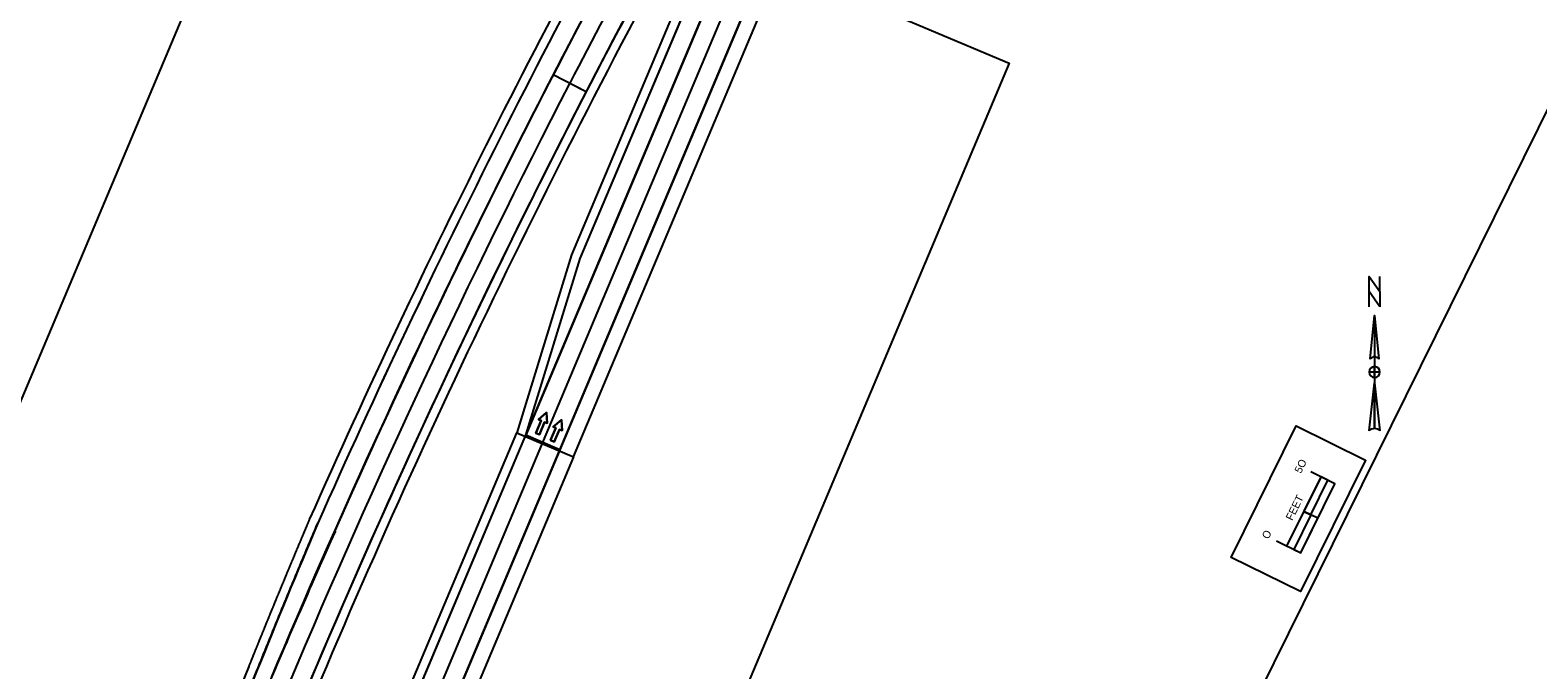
# Model space of a CAD drawing. Extents: x 14104283 to 14120882, y 8635219 to 8671666.
# Drawn here: x 14118496 to 14119473, y 8668018 to 8668432 of the extents above; entities that cross this region are included whole.
import ezdxf

# ---------------------------------------------------------------- set-up
doc = ezdxf.new("R2010")
doc.units = 0
for name, color, linetype in [('Default', 7, 'Continuous'), ('dsnCellsNorthArrow', 7, 'Continuous'), ('dsnCellsScaleBlock', 7, 'Continuous'), ('dsnNonPlotable', 7, 'Continuous'), ('dsnPaintExistingBrokenLaneLineWhite', 7, 'Continuous'), ('dsnPaintExistingDottedLineWhite', 7, 'Continuous'), ('dsnPaintExistingEdgeLineLeftYellow', 7, 'Continuous'), ('dsnPaintExistingEdgeLineRightWhite', 7, 'Continuous'), ('dsnPaintExistingLaneLineWhite', 7, 'Continuous'), ('dsnShadingPaved', 7, 'Continuous'), ('dsnStgShadingPrevPav', 7, 'Continuous'), ('Level 2', 7, 'Continuous'), ('Level 5', 7, 'Continuous')]:
    doc.layers.add(name, color=color, linetype=linetype)

msp = doc.modelspace()

# ---------------------------------------------------------------- linework, layer by layer
at = {"layer": 'Default'}
for p, q in [((14118835.25, 8668403.13), (14118856.57, 8668392.12)), ((14118845.91, 8668397.62), (14118856.57, 8668392.12)), ((14118693.64, 8668107.64), (14118694.07, 8668107.45)), ((14118528.39, 8667730.93), (14118643.53, 8668017.62))]:
    msp.add_line(p, q, dxfattribs=at)
for centre, radius, start, end in [((14121955.85, 8666791.92), 3512, 144.95493, 152.69211), ((14123732.96, 8665874.38), 5512, 149.67774, 156.09858), ((14123732.96, 8665874.38), 5524, 150.3689, 153.23374), ((14121955.85, 8666791.92), 3488, 149.50762, 152.69211), ((14123732.96, 8665874.38), 5512, 152.69211, 153.16925), ((14123732.96, 8665874.38), 5488, 152.69211, 157.1633), ((14123732.96, 8665874.38), 5512, 153.16925, 157.1633), ((14123732.96, 8665874.38), 5524, 153.23374, 156.09858), ((14123767.91, 8665959.11), 5522.39, 157.04925, 158.11426), ((14123265.63, 8666052.94), 5012, 155.80033, 157.1633)]:
    msp.add_arc(centre, radius, start, end, dxfattribs=at)
at = {"layer": 'dsnCellsNorthArrow'}
for p, q in [((14119367.21, 8668247.06), (14119370.02, 8668218.89)), ((14119367.21, 8668247.06), (14119367.21, 8668173.81)), ((14119364.39, 8668218.89), (14119364.39, 8668218.89)), ((14119364.5, 8668219.15), (14119365.02, 8668219.73)), ((14119363.68, 8668172.4), (14119367.21, 8668203.39)), ((14119367.21, 8668206.91), (14119367.21, 8668206.91))]:
    msp.add_line(p, q, dxfattribs=at)
msp.add_lwpolyline([(14119370.73, 8668252.69), (14119363.68, 8668262.55), (14119363.68, 8668272.41), (14119370.73, 8668262.55)], close=True, dxfattribs=at)
for points in [[(14119363.68, 8668252.69), (14119363.68, 8668272.41), (14119370.73, 8668262.55), (14119370.73, 8668272.41)], [(14119364.39, 8668218.89), (14119367.21, 8668247.06), (14119367.21, 8668220.3)], [(14119367.21, 8668206.91), (14119367.21, 8668210.44), (14119363.68, 8668210.44)], [(14119370.73, 8668210.44), (14119367.21, 8668210.44), (14119367.21, 8668213.96)], [(14119367.21, 8668173.81), (14119367.21, 8668203.39), (14119370.73, 8668172.4)]]:
    msp.add_lwpolyline(points, dxfattribs=at)
for centre, radius, start, end in [((14119367.21, 8668216.77), 3.52, 90.02039, 143.12574), ((14119367.21, 8668216.78), 3.52, 36.84806, 90.02184), ((14119367.21, 8668210.44), 3.52, 90, 180), ((14119367.21, 8668210.44), 3.52, 180, 270), ((14119367.21, 8668210.44), 3.52, 0, 90), ((14119367.21, 8668210.44), 3.52, 270, 360), ((14119367.21, 8668168.71), 5.1, 89.98939, 133.61895), ((14119367.21, 8668168.71), 5.11, 46.40206, 90.00064)]:
    msp.add_arc(centre, radius, start, end, dxfattribs=at)
at = {"layer": 'dsnCellsScaleBlock'}
msp.add_line((14119330.43, 8668115.73), (14119321.47, 8668120.16), dxfattribs=at)
msp.add_line((14119330.43, 8668115.73), (14119321.47, 8668120.16), dxfattribs=at)
for points in [[(14119274.42, 8668090.43), (14119316.53, 8668175.59), (14119361.35, 8668153.43), (14119319.24, 8668068.27)], [(14119319.24, 8668068.27), (14119274.42, 8668090.43), (14119316.53, 8668175.59), (14119361.35, 8668153.43)], [(14119325.92, 8668117.96), (14119337, 8668140.37), (14119332.55, 8668142.57), (14119321.47, 8668120.16)], [(14119319.35, 8668093.32), (14119330.43, 8668115.73), (14119325.92, 8668117.96), (14119314.84, 8668095.55)]]:
    msp.add_lwpolyline(points, close=True, dxfattribs=at)
for points in [[(14119303.67, 8668101.07), (14119319.35, 8668093.32), (14119341.51, 8668138.14), (14119325.83, 8668145.89)], [(14119310.39, 8668097.75), (14119332.55, 8668142.57)]]:
    msp.add_lwpolyline(points, dxfattribs=at)
at = {"layer": 'dsnNonPlotable'}
for points in [[(14118092.03, 8667853.71), (14118786.76, 8669258.84), (14119692.14, 8668811.2), (14118997.41, 8667406.07)], [(14118056.48, 8667161.91), (14118665.06, 8668606.45), (14119130.44, 8668410.38), (14118521.87, 8666965.84)]]:
    msp.add_lwpolyline(points, close=True, dxfattribs=at)
at = {"layer": 'dsnPaintExistingBrokenLaneLineWhite'}
for p, q in [((14118863.73, 8668248.6), (14118951.74, 8668457.58)), ((14114932.53, 8658913.38), (14118863.73, 8668248.6))]:
    msp.add_line(p, q, dxfattribs=at)
for centre, radius, start, end in [((14121955.85, 8666791.92), 3500, 149.50762, 152.69211), ((14123732.96, 8665874.38), 5500, 152.69211, 157.1633)]:
    msp.add_arc(centre, radius, start, end, dxfattribs=at)
at = {"layer": 'dsnPaintExistingDottedLineWhite'}
msp.add_arc((14123732.96, 8665874.38), 5512, 152.23375, 154.51073, dxfattribs=at)
at = {"layer": 'dsnPaintExistingEdgeLineLeftYellow'}
for p, q in [((14118852.57, 8668283.93), (14118948.15, 8668509.94)), ((14118817.44, 8668169.6), (14118852.57, 8668283.93)), ((14115900.95, 8661243.95), (14118817.44, 8668169.6))]:
    msp.add_line(p, q, dxfattribs=at)
for centre, radius, start, end in [((14121955.85, 8666791.92), 3488, 149.50762, 152.69211), ((14123732.96, 8665874.38), 5488, 152.69211, 157.1633)]:
    msp.add_arc(centre, radius, start, end, dxfattribs=at)
at = {"layer": 'dsnPaintExistingEdgeLineRightWhite'}
for p, q in [((14118874.68, 8668243.67), (14118962.79, 8668452.92)), ((14110924.38, 8649364.51), (14118874.67, 8668243.66)), ((14118643.53, 8668017.62), (14118412.94, 8667444.38))]:
    msp.add_line(p, q, dxfattribs=at)
for centre, radius, start, end in [((14123732.96, 8665874.38), 5524, 150.3689, 156.09858), ((14123767.91, 8665959.11), 5522.39, 157.04925, 158.11426)]:
    msp.add_arc(centre, radius, start, end, dxfattribs=at)
at = {"layer": 'dsnPaintExistingLaneLineWhite'}
msp.add_line((14118863.63, 8668279.27), (14118940.68, 8668462.24), dxfattribs=at)
at = {"layer": 'dsnShadingPaved'}
for points in [[(14118817.44, 8668169.6), (14118852.57, 8668283.93), (14118948.15, 8668509.94), (14118959.14, 8668505.1), (14118940.68, 8668462.24)], [(14118817.44, 8668169.6), (14118940.68, 8668462.24), (14118962.79, 8668452.92), (14118874.67, 8668243.66), (14118839.45, 8668160.02)], [(14118227.72, 8666769.23), (14118817.44, 8668169.6), (14118839.45, 8668160.02), (14118249.84, 8666759.92)]]:
    msp.add_lwpolyline(points, close=True, dxfattribs=at)
at = {"layer": 'dsnStgShadingPrevPav'}
for p, q in [((14118924.09, 8668469.22), (14118847.04, 8668286.26)), ((14118848.39, 8668155.49), (14118972.01, 8668449.04)), ((14118847.04, 8668286.26), (14118811.53, 8668171.01)), ((14115895.65, 8661246.83), (14118811.53, 8668171.01)), ((14118811.53, 8668171.01), (14118848.39, 8668155.49)), ((14118811.53, 8668171.01), (14118848.39, 8668155.49)), ((14118848.39, 8668155.49), (14115932.51, 8661231.3)), ((14118637.96, 8668019.85), (14118497.16, 8667669.27))]:
    msp.add_line(p, q, dxfattribs=at)
for centre, radius, start, end in [((14123732.96, 8665874.38), 5512, 146.42562, 157.1633), ((14123732.96, 8665874.38), 5488, 146.42119, 157.1633), ((14123732.96, 8665874.38), 5530, 150.3689, 156.09911), ((14123732.59, 8665873.82), 5512, 150.36196, 157.1633), ((14123732.96, 8665874.38), 5524, 150.3689, 156.09858), ((14123732.96, 8665874.38), 5524, 150.3689, 156.09858), ((14123732.96, 8665874.38), 5488, 150.67095, 157.1633), ((14123732.96, 8665874.38), 5482, 150.67097, 157.1633)]:
    msp.add_arc(centre, radius, start, end, dxfattribs=at)
for points, degree in [([(14118677.15, 8668114.84), (14118676.77, 8668113.95), (14118675.45, 8668110.85), (14118673.07, 8668105.18), (14118671.18, 8668100.7), (14118669.16, 8668095.89), (14118667.19, 8668091.17), (14118665.21, 8668086.42), (14118663.23, 8668081.68), (14118661.26, 8668076.94), (14118659.29, 8668072.19), (14118657.33, 8668067.44), (14118655.38, 8668062.69), (14118653.42, 8668057.94), (14118651.47, 8668053.18), (14118649.53, 8668048.43), (14118647.59, 8668043.66), (14118645.66, 8668038.92), (14118643.7, 8668034.09), (14118641.88, 8668029.58), (14118639.58, 8668023.88), (14118638.32, 8668020.76), (14118637.96, 8668019.85)], 2), ([(14118643.53, 8668017.62), (14118644.16, 8668019.2), (14118645.44, 8668022.38), (14118647.36, 8668027.14), (14118649.28, 8668031.89), (14118651.21, 8668036.65), (14118653.15, 8668041.4), (14118655.08, 8668046.16), (14118657.03, 8668050.91), (14118658.97, 8668055.66), (14118660.92, 8668060.4), (14118662.88, 8668065.15), (14118664.84, 8668069.89), (14118666.8, 8668074.63), (14118668.77, 8668079.37), (14118670.74, 8668084.11), (14118672.72, 8668088.85), (14118674.7, 8668093.58), (14118676.69, 8668098.32), (14118678.68, 8668103.05), (14118680.67, 8668107.78), (14118682.01, 8668110.93), (14118682.67, 8668112.51)], 3), ([(14118643.53, 8668017.62), (14118644.16, 8668019.2), (14118645.44, 8668022.38), (14118647.36, 8668027.14), (14118649.28, 8668031.89), (14118651.21, 8668036.65), (14118653.15, 8668041.4), (14118655.08, 8668046.16), (14118657.03, 8668050.91), (14118658.97, 8668055.66), (14118660.92, 8668060.4), (14118662.88, 8668065.15), (14118664.84, 8668069.89), (14118666.8, 8668074.63), (14118668.77, 8668079.37), (14118670.74, 8668084.11), (14118672.72, 8668088.85), (14118674.7, 8668093.58), (14118676.69, 8668098.32), (14118678.68, 8668103.05), (14118680.67, 8668107.78), (14118682.01, 8668110.93), (14118682.67, 8668112.51)], 3)]:
    msp.add_open_spline(points, degree=degree, dxfattribs=at)
at = {"layer": 'Level 2'}
for points in [[(14118823.95, 8668170.96), (14118826.25, 8668169.99), (14118829.65, 8668178.06), (14118831.38, 8668177.33), (14118830.92, 8668184.3), (14118825.62, 8668179.76), (14118827.34, 8668179.03)], [(14118833.5, 8668166.24), (14118835.8, 8668165.27), (14118839.2, 8668173.34), (14118840.93, 8668172.61), (14118840.47, 8668179.58), (14118835.17, 8668175.03), (14118836.89, 8668174.31)]]:
    msp.add_lwpolyline(points, close=True, dxfattribs=at)
at = {"layer": 'Level 5'}
for points in [[(14118827.34, 8668179.03), (14118825.62, 8668179.76), (14118830.92, 8668184.3), (14118831.38, 8668177.33), (14118829.65, 8668178.06), (14118826.25, 8668169.99), (14118823.95, 8668170.96), (14118827.34, 8668179.03)], [(14118836.89, 8668174.31), (14118835.17, 8668175.03), (14118840.47, 8668179.58), (14118840.93, 8668172.61), (14118839.2, 8668173.34), (14118835.8, 8668165.27), (14118833.5, 8668166.24), (14118836.89, 8668174.31)]]:
    msp.add_lwpolyline(points, dxfattribs=at)

# ---------------------------------------------------------------- texts
at = {"layer": 'dsnCellsScaleBlock'}
for s, p in [('5O', (14119319.54, 8668144.46)), ('FEET', (14119313.9, 8668113.89)), ('O', (14119298.46, 8668101.83))]:
    msp.add_text(s, height=5, rotation=63.69117, dxfattribs=at).set_placement(p)

doc.saveas('drawing.dxf')
